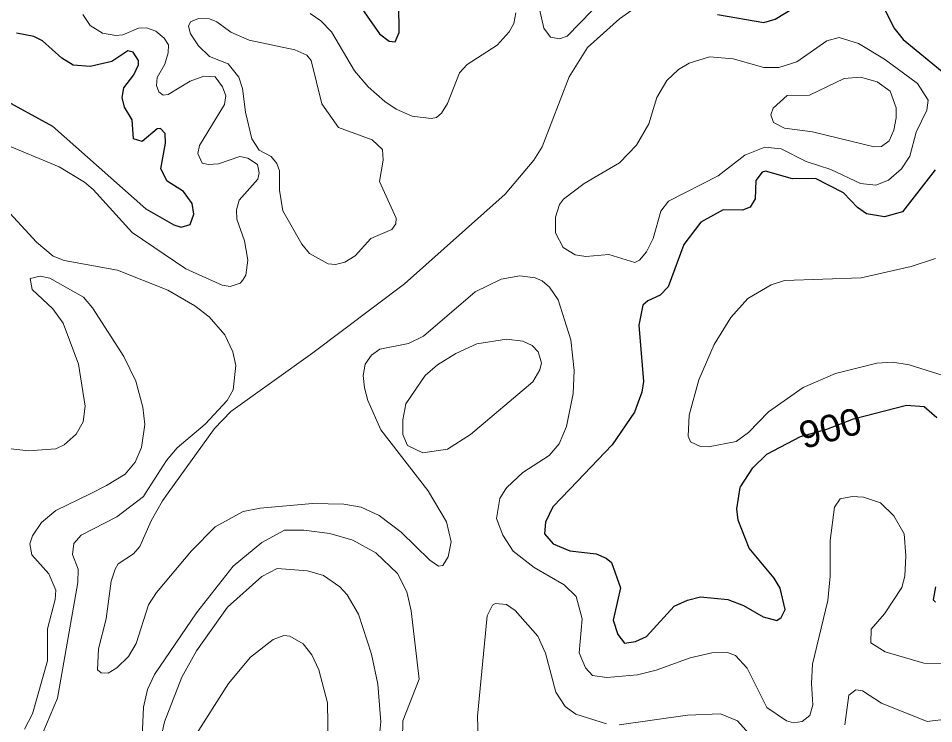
# Model space of a CAD drawing. Extents: x 473.9 to 500, y 7733.1 to 7760.8.
# Drawn here: x 482.142 to 484.875, y 7748.942 to 7751.048 of the extents above; entities that cross this region are included whole.
import ezdxf
from ezdxf.enums import TextEntityAlignment as Align

# ---------------------------------------------------------------- set-up
doc = ezdxf.new("R2010")
doc.units = 0
doc.header["$LTSCALE"] = 0.032
doc.layers.add('1', color=7, linetype='Continuous', lineweight=25)
doc.layers.add('2', color=7, linetype='Continuous', lineweight=13)
doc.layers.add('61', color=7, linetype='Continuous')

msp = doc.modelspace()

# ---------------------------------------------------------------- linework, layer by layer
at = {"layer": '1'}
for points in [[(483.1534, 7751.0966), (483.2206, 7751.0013), (483.249, 7750.9792), (483.2676, 7750.978), (483.2793, 7751.005), (483.2784, 7751.0898)], [(484.2294, 7751.0596), (484.3673, 7751.0351), (484.4012, 7751.045), (484.4617, 7751.0819)], [(484.7272, 7751.078), (484.7555, 7751.0191), (484.7835, 7750.9846), (484.9, 7750.8895)], [(482.3059, 7750.9075), (482.2722, 7750.9288), (482.2148, 7750.9803), (482.1889, 7750.9931), (482.1368, 7751.0031)], [(482.088, 7750.8112), (482.2448, 7750.7258), (482.5228, 7750.4787), (482.6061, 7750.431), (482.6286, 7750.4241), (482.6552, 7750.4322), (482.6665, 7750.4635), (482.6617, 7750.4953), (482.6349, 7750.5304), (482.5871, 7750.5619), (482.5673, 7750.5985), (482.5818, 7750.6748), (482.5807, 7750.7038), (482.5663, 7750.7186), (482.5563, 7750.7182), (482.512, 7750.6803), (482.4858, 7750.6876), (482.4823, 7750.7449), (482.4596, 7750.7821), (482.452, 7750.8115), (482.4574, 7750.8398), (482.4872, 7750.8786), (482.5008, 7750.909), (482.5006, 7750.9223), (482.4847, 7750.9472), (482.469, 7750.9506), (482.4218, 7750.9184), (482.3563, 7750.904), (482.3059, 7750.9075)], [(484.8787, 7750.5953), (484.7815, 7750.4702), (484.7279, 7750.4547), (484.6735, 7750.4642), (484.6472, 7750.4825), (484.6051, 7750.5268), (484.5221, 7750.5698), (484.4534, 7750.5682), (484.3722, 7750.591), (484.3621, 7750.5885), (484.3439, 7750.5631), (484.3412, 7750.5089), (484.3266, 7750.4836), (484.3042, 7750.4748), (484.2458, 7750.4761), (484.1794, 7750.4388), (484.1289, 7750.3721), (484.0818, 7750.2465), (484.058, 7750.221), (484.0209, 7750.2047), (484.0068, 7750.1918), (483.9948, 7750.1321), (484.0086, 7749.9637), (484.0039, 7749.9316), (483.9817, 7749.8719), (483.9148, 7749.7747), (483.7881, 7749.6419), (483.7376, 7749.5889), (483.7157, 7749.5432), (483.7133, 7749.5081), (483.7385, 7749.4792), (483.7884, 7749.4577), (483.8675, 7749.449), (483.8974, 7749.4363), (483.9129, 7749.4226), (483.9401, 7749.3473), (483.9177, 7749.2507), (483.9315, 7749.208), (483.952, 7749.182), (483.9848, 7749.1867), (484.0169, 7749.2023), (484.1004, 7749.2922), (484.1399, 7749.311), (484.1786, 7749.3204), (484.2605, 7749.313), (484.3071, 7749.295), (484.3654, 7749.2603), (484.4064, 7749.2497), (484.4197, 7749.2584), (484.4312, 7749.2823), (484.4161, 7749.3466), (484.3984, 7749.3766), (484.3238, 7749.4657), (484.2913, 7749.5496), (484.2869, 7749.5832), (484.2974, 7749.6467), (484.2977, 7749.6485), (484.335, 7749.7061), (484.3768, 7749.7461), (484.4771, 7749.7993), (484.5555, 7749.8216)], [(484.5555, 7749.8216), (484.6351, 7749.8524), (484.7934, 7749.8932), (484.8462, 7749.8884), (484.8835, 7749.8559)], [(484.8796, 7749.3504), (484.8734, 7749.3112), (484.8796, 7749.3041)]]:
    msp.add_lwpolyline(points, dxfattribs=at)
at = {"layer": '2'}
for points in [[(482.7278, 7749.8226), (482.7769, 7749.8741), (483.0213, 7750.0486), (483.2955, 7750.2552), (483.5954, 7750.5229), (483.6806, 7750.6242), (483.7063, 7750.6636), (483.7867, 7750.8727), (483.8414, 7750.9611), (483.9363, 7751.0463), (484.0175, 7751.1042)], [(483.6994, 7751.0709), (483.7107, 7751.0179), (483.7306, 7750.9915), (483.7574, 7750.9862), (483.781, 7750.9949), (483.8918, 7751.1098)], [(482.3347, 7751.0592), (482.3572, 7751.0262), (482.3934, 7751.0037), (482.4336, 7750.9965), (482.4545, 7750.9981), (482.5011, 7751.0182), (482.5252, 7751.0198), (482.5526, 7751.0093), (482.5775, 7750.9884), (482.5903, 7750.9684), (482.5895, 7750.945), (482.5799, 7750.9113), (482.5566, 7750.8711), (482.555, 7750.847), (482.5622, 7750.8285), (482.5751, 7750.8188), (482.5895, 7750.8204), (482.6555, 7750.8598), (482.6957, 7750.8751), (482.7294, 7750.8727), (482.7519, 7750.8437), (482.7616, 7750.8164), (482.7576, 7750.7907), (482.6836, 7750.6685), (482.678, 7750.6443), (482.6908, 7750.6154), (482.7101, 7750.6114), (482.7399, 7750.6138), (482.8034, 7750.6355), (482.8275, 7750.6307), (482.8565, 7750.6114), (482.8613, 7750.5864), (482.8573, 7750.5672), (482.8018, 7750.5044), (482.7937, 7750.4755), (482.7945, 7750.4482), (482.8171, 7750.3838), (482.8275, 7750.3259), (482.8219, 7750.2809), (482.8114, 7750.2648), (482.8042, 7750.2568), (482.7745, 7750.2471), (482.7503, 7750.2512), (482.6426, 7750.3002), (482.4826, 7750.4087)], [(483.6275, 7751.064), (483.6211, 7751.0319), (483.6074, 7751.0078), (483.5712, 7750.9675), (483.482, 7750.9096), (483.4587, 7750.8855), (483.4233, 7750.7939), (483.4056, 7750.7649), (483.3903, 7750.7521), (483.3743, 7750.7489), (483.318, 7750.7561), (483.2697, 7750.777), (483.2368, 7750.7995), (483.1869, 7750.8437), (483.1459, 7750.8912), (483.0768, 7751.0078), (483.0454, 7751.0399), (483.0132, 7751.0624)], [(482.4826, 7750.4087), (482.366, 7750.5366), (482.3403, 7750.5583), (482.2647, 7750.6041), (482.0918, 7750.6757)], [(482.1059, 7750.4775), (482.1963, 7750.379), (482.2466, 7750.3374), (482.2796, 7750.325), (482.4379, 7750.2955)], [(484.8799, 7750.3311), (484.8075, 7750.3071), (484.6579, 7750.2727), (484.4291, 7750.2651), (484.3899, 7750.2525), (484.3193, 7750.2113), (484.2694, 7750.1543), (484.2196, 7750.0739), (484.1731, 7749.9684), (484.1451, 7749.8633), (484.1421, 7749.8006), (484.1484, 7749.7837), (484.1782, 7749.7696), (484.2023, 7749.7679), (484.2849, 7749.7843), (484.3213, 7749.8114), (484.3817, 7749.8732), (484.4848, 7749.9452), (484.5813, 7749.9871), (484.7046, 7750.018), (484.7523, 7750.0211), (484.8011, 7750.013), (484.9216, 7749.975)], [(482.1608, 7748.9253), (482.1846, 7748.9714), (482.2292, 7749.1295), (482.2291, 7749.225), (482.2524, 7749.3123), (482.2541, 7749.3401), (482.2334, 7749.3894), (482.1829, 7749.4462), (482.1771, 7749.4788), (482.1849, 7749.5022), (482.2112, 7749.5423), (482.2548, 7749.5783), (482.3565, 7749.6285), (482.4056, 7749.6527), (482.4612, 7749.6871), (482.4913, 7749.7228), (482.5105, 7749.7662), (482.5195, 7749.8349), (482.5139, 7749.8869), (482.4935, 7749.9646), (482.4568, 7750.038), (482.3637, 7750.1837), (482.3369, 7750.2148), (482.2365, 7750.272), (482.2073, 7750.2776), (482.1781, 7750.271), (482.1833, 7750.2379), (482.2449, 7750.1807), (482.2761, 7750.1372), (482.3215, 7750.015), (482.3418, 7749.8901), (482.3354, 7749.8434), (482.3152, 7749.8058), (482.2796, 7749.7739), (482.254, 7749.762), (482.173, 7749.7567), (482.0765, 7749.767)], [(482.4379, 7750.2955), (482.589, 7750.236), (482.6687, 7750.1897), (482.7116, 7750.1562), (482.759, 7750.1023), (482.7828, 7750.0519), (482.792, 7750.0107), (482.7832, 7749.9384), (482.7658, 7749.9067), (482.6996, 7749.8362), (482.6165, 7749.7658), (482.5848, 7749.7276), (482.5222, 7749.63), (482.5159, 7749.6203), (482.4359, 7749.5598), (482.3297, 7749.5048), (482.3078, 7749.4802), (482.3036, 7749.4468), (482.3207, 7749.4034), (482.3202, 7749.3632), (482.2588, 7749.018), (482.2156, 7748.9141)], [(484.7885, 7749.382), (484.7917, 7749.4431), (484.7861, 7749.5082), (484.7555, 7749.5621), (484.7154, 7749.6007), (484.6655, 7749.6176), (484.6317, 7749.62), (484.5955, 7749.6128), (484.5787, 7749.5879), (484.5658, 7749.4882), (484.5658, 7749.382), (484.5586, 7749.3097), (484.5127, 7749.1199), (484.5095, 7749.062), (484.5143, 7748.9977), (484.5047, 7748.9664), (484.4822, 7748.9487), (484.4565, 7748.9438), (484.4356, 7748.9503), (484.3761, 7748.9905), (484.3174, 7749.1071), (484.2828, 7749.1456), (484.2587, 7749.1545), (484.212, 7749.1529), (484.1477, 7749.1384), (484.0464, 7749.1014), (483.9901, 7749.0878), (483.8985, 7749.0797), (483.8559, 7749.0861), (483.8357, 7749.1087), (483.8165, 7749.1537), (483.8253, 7749.255), (483.8076, 7749.3217), (483.7714, 7749.3563), (483.6822, 7749.4078), (483.6195, 7749.4568), (483.5881, 7749.5042), (483.5696, 7749.5541), (483.5793, 7749.6136), (483.5957, 7749.6401), (483.6002, 7749.6474), (483.6484, 7749.6916), (483.7264, 7749.7422), (483.7562, 7749.7776), (483.7787, 7749.8291), (483.798, 7749.9272), (483.8012, 7749.9963), (483.7915, 7750.088), (483.7537, 7750.207), (483.728, 7750.2455), (483.7063, 7750.264), (483.6846, 7750.2729), (483.6396, 7750.2785), (483.5833, 7750.2689), (483.5061, 7750.2311), (483.3517, 7750.0992), (483.3067, 7750.0767), (483.2215, 7750.0598), (483.1966, 7750.0421), (483.1781, 7750.0156), (483.1716, 7749.9818), (483.1757, 7749.9448), (483.1853, 7749.9063), (483.2239, 7749.8194), (483.3644, 7749.6379), (483.367, 7749.6345), (483.4201, 7749.5444), (483.4345, 7749.4849), (483.4257, 7749.4399), (483.4096, 7749.4142), (483.3968, 7749.4118), (483.3702, 7749.4295), (483.285, 7749.5131), (483.2191, 7749.5637), (483.1652, 7749.5887), (483.1138, 7749.5967), (483.0205, 7749.5991), (482.8645, 7749.5854), (482.8131, 7749.575), (482.7294, 7749.5292), (482.6595, 7749.4576), (482.555, 7749.3338), (482.5308, 7749.2968), (482.4938, 7749.181), (482.4713, 7749.1424), (482.4368, 7749.1087), (482.411, 7749.0926), (482.3901, 7749.0934), (482.3789, 7749.1022), (482.3821, 7749.1649), (482.4046, 7749.255), (482.4191, 7749.3676), (482.4311, 7749.4029), (482.4408, 7749.419), (482.4866, 7749.4488), (482.5051, 7749.4705), (482.5389, 7749.5477), (482.5726, 7749.6072), (482.5895, 7749.6307), (482.7278, 7749.8226)], [(482.5097, 7748.8572), (482.5161, 7748.9914), (482.5282, 7749.0437), (482.549, 7749.0889), (482.6744, 7749.273), (482.7836, 7749.4121), (482.8688, 7749.4827), (482.9368, 7749.5192), (482.9947, 7749.5194), (483.0723, 7749.5097), (483.1403, 7749.4901), (483.2097, 7749.4521), (483.2744, 7749.3901), (483.3023, 7749.3352), (483.3154, 7749.279), (483.3389, 7749.0743), (483.2899, 7748.9499), (483.2879, 7748.8415)], [(483.215, 7748.8577), (483.2239, 7748.9476), (483.215, 7749.0598), (483.197, 7749.1498), (483.1574, 7749.2689), (483.1235, 7749.3267), (483.1024, 7749.3506), (483.053, 7749.384), (483.0059, 7749.3984), (482.9154, 7749.405), (482.8692, 7749.3816), (482.7664, 7749.2894), (482.6741, 7749.1597), (482.63, 7749.0802), (482.5791, 7748.9477), (482.5275, 7748.7179)], [(484.9501, 7749.1215), (484.8456, 7749.1223), (484.7298, 7749.1561), (484.6872, 7749.1834), (484.688, 7749.2236), (484.7274, 7749.2695), (484.7797, 7749.3483), (484.7885, 7749.382)], [(483.5188, 7748.7571), (483.5126, 7748.9643), (483.5417, 7749.2634), (483.5578, 7749.2954), (483.5669, 7749.3005), (483.5993, 7749.2975), (483.6258, 7749.2798), (483.6932, 7749.2027), (483.7162, 7749.1526), (483.7465, 7749.0363), (483.7744, 7748.9929), (483.8064, 7748.9702), (483.8978, 7748.9412)], [(482.6672, 7748.9006), (482.77, 7749.0614), (482.8351, 7749.1404), (482.9026, 7749.1934), (482.9346, 7749.2055), (482.9532, 7749.2032), (482.9923, 7749.1803), (483.018, 7749.1472), (483.0395, 7749.1027), (483.0654, 7749.0035), (483.067, 7748.878)], [(484.6092, 7748.9386), (484.6209, 7749.027)], [(484.6209, 7749.027), (484.642, 7749.0433), (484.6616, 7749.0403), (484.7191, 7749.003), (484.8547, 7748.9479), (484.9195, 7748.9567)], [(483.9359, 7748.9382), (484.1397, 7748.9669), (484.2382, 7748.971), (484.2892, 7748.9499), (484.3483, 7748.8839)]]:
    msp.add_lwpolyline(points, dxfattribs=at)
for points in [[(483.27, 7750.4511), (483.2204, 7750.5605), (483.2318, 7750.6238), (483.2292, 7750.6557), (483.1988, 7750.6853), (483.0985, 7750.7221), (483.0478, 7750.7924), (483.0164, 7750.9215), (483.0036, 7750.9377), (482.968, 7750.9541), (482.8316, 7750.9827), (482.7768, 7751.0061), (482.7353, 7751.0378), (482.7126, 7751.0467), (482.6805, 7751.0472), (482.656, 7751.0369), (482.6505, 7751.0239), (482.6558, 7751.0011), (482.6799, 7750.9655), (482.7127, 7750.9342), (482.7688, 7750.9123), (482.8004, 7750.8721), (482.8119, 7750.8382), (482.82, 7750.7679), (482.8396, 7750.6878), (482.8617, 7750.6544), (482.8966, 7750.6348), (482.9137, 7750.614), (482.9218, 7750.5925), (482.9216, 7750.5347), (482.9318, 7750.4728), (482.9885, 7750.3739), (483.0116, 7750.3458), (483.0668, 7750.3146), (483.0895, 7750.3123), (483.1169, 7750.3198), (483.1474, 7750.3388), (483.1949, 7750.3907), (483.2569, 7750.417), (483.2694, 7750.4344)], [(484.7787, 7750.5985), (484.8029, 7750.6363), (484.8227, 7750.7076), (484.8537, 7750.7734), (484.8576, 7750.8039), (484.8262, 7750.8532), (484.728, 7750.9262), (484.6503, 7750.9727), (484.5924, 7750.9907), (484.5558, 7750.9808), (484.4663, 7750.9177), (484.4119, 7750.9014), (484.3678, 7750.9005), (484.2758, 7750.9273), (484.2055, 7750.9329), (484.1444, 7750.9134), (484.1132, 7750.8945), (484.0783, 7750.8626), (484.0485, 7750.811), (484.024, 7750.7332), (483.9873, 7750.6693), (483.9363, 7750.616), (483.8314, 7750.5544), (483.7694, 7750.5079), (483.7581, 7750.4921), (483.7459, 7750.4539), (483.7453, 7750.4076), (483.7688, 7750.3632), (483.804, 7750.342), (483.8367, 7750.3371), (483.9048, 7750.3427), (483.9827, 7750.3183), (483.9962, 7750.3255), (484.0169, 7750.3505), (484.0368, 7750.3908), (484.0597, 7750.4716), (484.0834, 7750.5019), (484.2314, 7750.5772), (484.3108, 7750.6392), (484.3706, 7750.6626), (484.4189, 7750.658), (484.4939, 7750.6207), (484.5678, 7750.5965), (484.6563, 7750.5549), (484.7014, 7750.5497), (484.7394, 7750.5645)], [(484.7625, 7750.7505), (484.7625, 7750.7805), (484.7449, 7750.8299), (484.7062, 7750.8586), (484.6564, 7750.8718), (484.607, 7750.8683), (484.504, 7750.8182), (484.437, 7750.8173), (484.395, 7750.7791), (484.3882, 7750.7596), (484.3969, 7750.7366), (484.429, 7750.7199), (484.5132, 7750.7093), (484.6966, 7750.6636), (484.7188, 7750.6654), (484.7413, 7750.6818), (484.7554, 7750.7136)], [(483.4923, 7749.805), (483.6776, 7749.9624), (483.6993, 7749.9984), (483.7038, 7750.0187), (483.6935, 7750.052), (483.6764, 7750.0706), (483.648, 7750.0836), (483.5999, 7750.0903), (483.5114, 7750.0759), (483.4487, 7750.047), (483.394, 7750.0127), (483.3566, 7749.9809), (483.2991, 7749.8971), (483.2904, 7749.8489), (483.2902, 7749.8054), (483.3038, 7749.7721), (483.3495, 7749.75), (483.423, 7749.7618)]]:
    msp.add_lwpolyline(points, close=True, dxfattribs=at)

# ---------------------------------------------------------------- texts
at = {"layer": '61', "width": 1.05}
msp.add_text('900', height=0.08, rotation=15.313, dxfattribs=at).set_placement((484.5766, 7749.7859), align=Align.CENTER)

doc.saveas('drawing.dxf')
